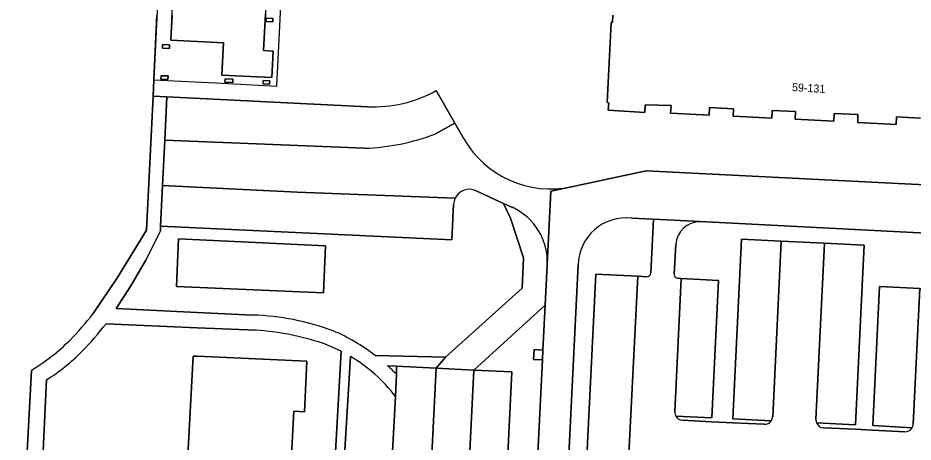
# Model space of a CAD drawing. Extents: x 161758 to 162722, y 384793 to 385405.
# Drawn here: x 161977.6 to 162089.5, y 385196.7 to 385249.7 of the extents above; entities that cross this region are included whole.
import ezdxf

# ---------------------------------------------------------------- set-up
doc = ezdxf.new("R2010")
doc.units = 0
for name, color, linetype in [('IMGEO_Erf', 7, 'Continuous'), ('IMGEO_Grasland_overig', 7, 'Continuous'), ('IMGEO_Groenvoorziening', 7, 'Continuous'), ('IMGEO_Pand', 7, 'Continuous'), ('IMGEO_Pand_nummerreeks', 7, 'Continuous'), ('IMGEO_Pand_overbouw', 7, 'Continuous'), ('IMGEO_Parkeervlak_open', 7, 'Continuous'), ('IMGEO_Rijbaan_lokaal_open', 7, 'Continuous'), ('IMGEO_Voetpad_open', 7, 'Continuous')]:
    doc.layers.add(name, color=color, linetype=linetype)

msp = doc.modelspace()

# ---------------------------------------------------------------- linework, layer by layer
at = {"layer": 'IMGEO_Erf'}
for points in [[(162046.78, 385228.58), (162056.08, 385230.58), (162089.27, 385228.91), (162119.21, 385227.48), (162120.58, 385255.07), (162121.52, 385275.66)], [(161993.66, 385223.17), (161994.48, 385239.89), (161994.58, 385241.94), (161994.97, 385250)], [(161994.97, 385250), (161994.58, 385241.94), (161994.48, 385239.89), (161996.2, 385239.8), (162021.28, 385238.58)], [(162008.52, 385250.18), (162008.29, 385245.58), (162009.5, 385245.52), (162009.33, 385242.21), (162003.07, 385242.52), (162003.27, 385246.56), (162000, 385246.72), (161996.7, 385246.89), (161996.86, 385250)], [(162090.36, 385237.16), (162087.39, 385237.32), (162087.34, 385236.37), (162082.53, 385236.62), (162082.57, 385237.59), (162079.6, 385237.71), (162079.55, 385236.76), (162074.73, 385237), (162074.77, 385237.97), (162071.83, 385238.09), (162071.79, 385237.15), (162066.96, 385237.39), (162067.01, 385238.33), (162064.01, 385238.47), (162063.96, 385237.53), (162059.16, 385237.78), (162059.21, 385238.72), (162055.96, 385238.82), (162055.93, 385237.87), (162051.36, 385238.14), (162051.42, 385239.07), (162051.22, 385239.1), (162051.71, 385249.1), (162051.88, 385249.1), (162051.93, 385250)], [(162029.86, 385240.58), (162032.18, 385236.54), (162033.31, 385234.57)], [(162040.78, 385219.71), (162039.13, 385224.67), (162038.29, 385226.51), (162034.86, 385228.09)], [(162032.03, 385226.37), (162031.81, 385221.96), (161995.42, 385223.67), (161995.39, 385223.09), (161993.57, 385219.42), (161991.69, 385216.2), (161989.87, 385213.4), (162000, 385212.9), (162006.94, 385212.56)], [(161986.98, 385212.75), (161990.02, 385217.24), (161993.66, 385223.17)], [(162022.22, 385207.53), (162031.04, 385207.3), (162040.59, 385215.92), (162040.78, 385219.71)], [(162007.35, 385210.66), (162000, 385210.99), (161988.6, 385211.49)], [(161981.18, 385204.49), (161980, 385179.69), (161982.83, 385179.54), (161985.81, 385179.38), (161985.88, 385180.71), (161988.86, 385180.55), (161988.93, 385181.91), (161991.96, 385181.75), (161992.03, 385183.14), (161995.24, 385182.97), (161995.39, 385185.95), (161998.34, 385185.8), (161999.48, 385207.45)], [(161999.48, 385207.45), (162000, 385207.43), (162013.69, 385206.82), (162013.41, 385200.48), (162012.08, 385200.55), (162011.09, 385181.64), (162016.49, 385181.38), (162017.99, 385208.04)], [(161977.59, 385173.79), (161979.29, 385205.66)]]:
    msp.add_lwpolyline(points, dxfattribs=at)
for points in [[(162009.46, 385249.59), (162009.43, 385249.17), (162008.58, 385249.21), (162008.61, 385249.64)], [(161996.55, 385246.31), (161996.53, 385245.85), (161995.65, 385245.9), (161995.67, 385246.35)], [(161996.36, 385242.41), (161996.34, 385241.96), (161995.46, 385242), (161995.48, 385242.45)], [(162004.45, 385242.03), (162004.43, 385241.6), (162003.45, 385241.65), (162003.47, 385242.07)], [(162009.07, 385241.81), (162009.05, 385241.38), (162008.22, 385241.42), (162008.24, 385241.85)], [(162015.78, 385215.32), (161997.42, 385216.14), (161997.66, 385222.07), (162016.03, 385221.19)]]:
    msp.add_lwpolyline(points, close=True, dxfattribs=at)
for centre, radius, start, end in [((162022.06, 385254.63), 16.07, 267.2007, 299.0331), ((162044.19, 385240.89), 12.58, 210.1487, 281.8576), ((162034.03, 385226.27), 2, 65.3426, 153.9899), ((162034.05, 385226.26), 2.02, 154.131, 177.0709), ((161953, 385239.24), 43.09, 316.225, 322.0594), ((162006.08, 385181.47), 31.1, 69.4775, 88.4165), ((161953.08, 385239.16), 45.03, 316.2341, 322.0816), ((162005.14, 385177.12), 33.62, 71.7297, 86.233), ((162007.09, 385187.73), 24.92, 52.6237, 66.6023), ((161964.64, 385229.39), 27.88, 301.6987, 314.3122), ((162008.93, 385190.22), 19.99, 63.0543, 70.2735), ((161967.52, 385226.13), 25.59, 302.2532, 314.9367)]:
    msp.add_arc(centre, radius, start, end, dxfattribs=at)
at = {"layer": 'IMGEO_Grasland_overig'}
for points in [[(162024.92, 385206.18), (162023.78, 385206.23)], [(162024.89, 385205.17), (162024.92, 385206.18)]]:
    msp.add_lwpolyline(points, dxfattribs=at)
msp.add_arc((162007.3, 385187.96), 24.61, 44.3667, 47.9501, dxfattribs=at)
at = {"layer": 'IMGEO_Groenvoorziening'}
for points in [[(162056.68, 385217.82), (162057.02, 385224.52), (162054.26, 385224.66)], [(162091.9, 385222.76), (162062.84, 385224.23)], [(162071.73, 385199.36), (162066.93, 385199.62), (162068.03, 385222.05), (162072.98, 385221.81), (162078.39, 385221.54), (162083.34, 385221.3), (162083.09, 385216.22), (162082.24, 385198.84), (162077.39, 385199.1)], [(162059.8, 385221.38), (162059.61, 385217.67)], [(162047.62, 385218.82), (162041.98, 385104.58), (162045.02, 385104.42), (162045.2, 385104.41), (162048.36, 385104.25)], [(162048.31, 385105.21), (162045.34, 385105.36), (162045.15, 385105.37), (162044.27, 385105.42), (162049.8, 385217.66), (162055.05, 385217.4)], [(162055.05, 385217.4), (162056.15, 385217.34)], [(162060.09, 385217.15), (162060.49, 385217.13), (162065.15, 385216.9), (162064.31, 385199.75), (162059.81, 385199.94)], [(162089.33, 385198.5), (162084.41, 385198.77), (162085.26, 385216.11), (162090.28, 385215.86), (162091.05, 385215.83)], [(162043.14, 385206.97), (162042.03, 385207.03), (162042.09, 385208.25), (162043.2, 385208.2), (162043.48, 385213.78), (162034.55, 385205.7), (162039.31, 385205.47), (162036.81, 385154.15), (162032.02, 385154.29), (162030.75, 385130.88), (162030.52, 385127.16)], [(162019.15, 385207.4), (162017.59, 385181.32), (162023.62, 385181.03), (162024.79, 385202.4)], [(162039.22, 385129.2), (162039.38, 385132.01), (162043.14, 385206.97)], [(162060.63, 385199.43), (162064.28, 385199.25), (162066.91, 385199.13), (162070.86, 385198.93)], [(162078.26, 385198.49), (162082.22, 385198.3), (162084.38, 385198.19), (162088.41, 385197.99)]]:
    msp.add_lwpolyline(points, dxfattribs=at)
for centre, radius, start, end in [((162053.57, 385218.75), 5.95, 83.3807, 179.2642), ((162062.8, 385221.22), 3, 89.244, 177.0607), ((162056.17, 385217.85), 0.505, 267.7544, 356.5094), ((162060.11, 385217.65), 0.499, 176.9571, 267.3181), ((162008.94, 385190.23), 19.98, 37.5275, 59.2711), ((162060.68, 385200.43), 0.997, 209.3025, 267.2649), ((162070.91, 385199.93), 1, 267.2313, 324.9443), ((162078.31, 385199.49), 1, 202.6886, 267.134), ((162088.45, 385199), 1, 267.3236, 330.4891)]:
    msp.add_arc(centre, radius, start, end, dxfattribs=at)
at = {"layer": 'IMGEO_Pand'}
for points in [[(161996.86, 385250), (161996.7, 385246.89), (162000, 385246.72), (162003.27, 385246.56), (162003.07, 385242.52), (162009.33, 385242.21), (162009.5, 385245.52), (162008.29, 385245.58), (162008.52, 385250.18)], [(162051.93, 385250), (162051.88, 385249.1), (162051.71, 385249.1), (162051.22, 385239.1), (162051.42, 385239.07), (162051.36, 385238.14), (162055.93, 385237.87), (162055.96, 385238.82), (162059.21, 385238.72), (162059.16, 385237.78), (162063.96, 385237.53), (162064.01, 385238.47), (162067.01, 385238.33), (162066.96, 385237.39), (162071.79, 385237.15), (162071.83, 385238.09), (162074.77, 385237.97), (162074.73, 385237), (162079.55, 385236.76), (162079.6, 385237.71), (162082.57, 385237.59), (162082.53, 385236.62), (162087.34, 385236.37), (162087.39, 385237.32), (162090.36, 385237.16)], [(162011.09, 385181.64), (162012.08, 385200.55), (162013.41, 385200.48), (162013.69, 385206.82), (162000, 385207.43), (161999.48, 385207.45), (161998.34, 385185.8)]]:
    msp.add_lwpolyline(points, dxfattribs=at)
for points in [[(162009.46, 385249.59), (162008.61, 385249.64), (162008.58, 385249.21), (162009.43, 385249.17)], [(161996.55, 385246.31), (161995.67, 385246.35), (161995.65, 385245.9), (161996.53, 385245.85)], [(161996.36, 385242.41), (161995.48, 385242.45), (161995.46, 385242), (161996.34, 385241.96)], [(162004.45, 385242.03), (162003.47, 385242.07), (162003.45, 385241.65), (162004.43, 385241.6)], [(162009.07, 385241.81), (162008.24, 385241.85), (162008.22, 385241.42), (162009.05, 385241.38)]]:
    msp.add_lwpolyline(points, close=True, dxfattribs=at)
at = {"layer": 'IMGEO_Pand_overbouw'}
msp.add_lwpolyline([(161996.7, 385246.89), (161999.09, 385295.28), (161997.18, 385295.37), (161994.58, 385241.94), (162003.1, 385241.51), (162009.95, 385241.16), (162010.78, 385257.89), (162008.91, 385257.98), (162008.52, 385250.18), (162008.29, 385245.58), (162009.5, 385245.52), (162009.33, 385242.21), (162003.07, 385242.52), (162003.27, 385246.56)], close=True, dxfattribs=at)
at = {"layer": 'IMGEO_Parkeervlak_open'}
for points in [[(162021.28, 385238.58), (161996.2, 385239.8), (161995.94, 385234.41), (162020.92, 385233.39)], [(162032.18, 385236.54), (162029.86, 385240.58)], [(162029.71, 385235.16), (162032.18, 385236.54)], [(162032.23, 385227.15), (162012.49, 385227.9), (161995.66, 385228.72), (161995.42, 385223.67), (162031.81, 385221.96), (162032.03, 385226.37)], [(162072.98, 385221.81), (162068.03, 385222.05), (162066.93, 385199.62), (162071.73, 385199.36)], [(162071.91, 385199.88), (162072.98, 385221.81)], [(162078.39, 385221.54), (162077.31, 385199.54)], [(162077.39, 385199.1), (162082.24, 385198.84), (162083.09, 385216.22), (162083.34, 385221.3), (162078.39, 385221.54)], [(162055.05, 385217.4), (162049.8, 385217.66), (162044.27, 385105.42), (162045.15, 385105.37), (162045.34, 385105.36), (162048.31, 385105.21)], [(162049.36, 385104.7), (162055.05, 385217.4)], [(162060.49, 385217.13), (162059.68, 385200.48)], [(162059.81, 385199.94), (162064.31, 385199.75), (162065.15, 385216.9), (162060.49, 385217.13)], [(162090.28, 385215.86), (162085.26, 385216.11), (162084.41, 385198.77), (162089.33, 385198.5)], [(162089.46, 385198.94), (162090.28, 385215.86)], [(162029.85, 385205.93), (162024.92, 385206.18), (162024.89, 385205.17), (162024.79, 385202.4), (162023.62, 385181.03), (162026.61, 385180.88)], [(162028.71, 385182.78), (162029.85, 385205.93)]]:
    msp.add_lwpolyline(points, dxfattribs=at)
msp.add_lwpolyline([(162034.55, 385205.7), (162032.02, 385154.29), (162036.81, 385154.15), (162039.31, 385205.47)], close=True, dxfattribs=at)
for centre, radius, start, end in [((162022.06, 385254.63), 16.07, 267.2007, 299.0331), ((162020.03, 385260.55), 27.17, 271.8635, 290.8566), ((162034.05, 385226.26), 2.02, 154.131, 177.0709), ((162060.67, 385200.43), 0.993, 177.0092, 209.46), ((162070.91, 385199.93), 0.998, 324.9271, 357.1565), ((162078.32, 385199.49), 1.01, 177.3282, 202.5371), ((162088.46, 385198.99), 0.997, 330.502, 357.1968)]:
    msp.add_arc(centre, radius, start, end, dxfattribs=at)
at = {"layer": 'IMGEO_Rijbaan_lokaal_open'}
for points in [[(162033.31, 385234.57), (162032.18, 385236.54), (162029.71, 385235.16)], [(162020.92, 385233.39), (161995.94, 385234.41), (161995.66, 385228.72), (162012.49, 385227.9), (162032.23, 385227.15)], [(162043.74, 385218.82), (162044.2, 385228.02), (162046.78, 385228.58)], [(162034.86, 385228.09), (162038.29, 385226.51), (162039.38, 385226.01)], [(162062.84, 385224.23), (162057.02, 385224.52), (162056.68, 385217.82)], [(162077.31, 385199.54), (162078.39, 385221.54), (162072.98, 385221.81), (162071.91, 385199.88)], [(162059.61, 385217.67), (162059.8, 385221.38)], [(162056.15, 385217.34), (162055.05, 385217.4), (162049.36, 385104.7)], [(162059.68, 385200.48), (162060.49, 385217.13), (162060.09, 385217.15)], [(162091.05, 385215.83), (162090.28, 385215.86), (162089.46, 385198.94)], [(162034.55, 385205.7), (162029.85, 385205.93), (162028.71, 385182.78)], [(162030.52, 385127.16), (162030.75, 385130.88), (162032.02, 385154.29), (162034.55, 385205.7)], [(162070.86, 385198.93), (162066.91, 385199.13), (162064.28, 385199.25), (162060.63, 385199.43)], [(162088.41, 385197.99), (162084.38, 385198.19), (162082.22, 385198.3), (162078.26, 385198.49)]]:
    msp.add_lwpolyline(points, dxfattribs=at)
for centre, radius, start, end in [((162020.03, 385260.55), 27.17, 271.8635, 290.8566), ((162044.19, 385240.89), 12.58, 210.1487, 281.8576), ((162034.03, 385226.27), 2, 65.3426, 153.9899), ((162036.2, 385219.17), 7.55, 357.386, 65.0628), ((162062.8, 385221.22), 3, 89.244, 177.0607), ((162056.17, 385217.85), 0.505, 267.7544, 356.5094), ((162060.11, 385217.65), 0.499, 176.9571, 267.3181), ((162060.67, 385200.43), 0.993, 177.0092, 209.46), ((162060.68, 385200.43), 0.997, 209.3025, 267.2649), ((162070.91, 385199.93), 1, 267.2313, 324.9443), ((162070.91, 385199.93), 0.998, 324.9271, 357.1565), ((162078.32, 385199.49), 1.01, 177.3282, 202.5371), ((162078.31, 385199.49), 1, 202.6886, 267.134), ((162088.45, 385199), 1, 267.3236, 330.4891), ((162088.46, 385198.99), 0.997, 330.502, 357.1968)]:
    msp.add_arc(centre, radius, start, end, dxfattribs=at)
at = {"layer": 'IMGEO_Voetpad_open'}
for points in [[(162006.94, 385212.56), (162000, 385212.9), (161989.87, 385213.4), (161991.69, 385216.2), (161993.57, 385219.42), (161995.39, 385223.09), (161995.42, 385223.67), (161995.66, 385228.72), (161995.94, 385234.41), (161996.2, 385239.8), (161994.48, 385239.89), (161993.66, 385223.17), (161990.02, 385217.24), (161986.98, 385212.75)], [(162054.26, 385224.66), (162057.02, 385224.52), (162062.84, 385224.23), (162091.9, 385222.76), (162092.09, 385222.75), (162097.16, 385222.5), (162118.91, 385221.44), (162119.21, 385227.48), (162089.27, 385228.91), (162056.08, 385230.58), (162046.78, 385228.58), (162044.2, 385228.02), (162043.74, 385218.82), (162043.48, 385213.78), (162043.2, 385208.2), (162043.14, 385206.97), (162039.38, 385132.01), (162039.22, 385129.2)], [(162039.38, 385226.01), (162038.29, 385226.51), (162039.13, 385224.67), (162040.78, 385219.71), (162040.59, 385215.92), (162031.04, 385207.3), (162029.85, 385205.93), (162034.55, 385205.7), (162043.48, 385213.78)], [(162040, 385065.39), (162040.05, 385066.31), (162041.62, 385097.36), (162041.67, 385098.19), (162041.79, 385100.78), (162041.8, 385100.87), (162041.98, 385104.58), (162047.62, 385218.82)], [(162043.48, 385213.78), (162043.74, 385218.82)], [(161988.6, 385211.49), (162000, 385210.99), (162007.35, 385210.66)], [(162017.99, 385208.04), (162016.49, 385181.38), (162017.59, 385181.32), (162019.15, 385207.4)], [(162023.78, 385206.23), (162024.92, 385206.18), (162029.85, 385205.93), (162031.04, 385207.3), (162022.22, 385207.53)], [(161979.29, 385205.66), (161977.59, 385173.79)], [(162024.79, 385202.4), (162024.89, 385205.17)], [(161979.69, 385173.74), (161980, 385179.69), (161981.18, 385204.49)]]:
    msp.add_lwpolyline(points, dxfattribs=at)
for points in [[(161997.66, 385222.07), (161997.42, 385216.14), (162015.78, 385215.32), (162016.03, 385221.19)], [(162043.2, 385208.2), (162042.09, 385208.25), (162042.03, 385207.03), (162043.14, 385206.97)]]:
    msp.add_lwpolyline(points, close=True, dxfattribs=at)
for centre, radius, start, end in [((162036.2, 385219.17), 7.55, 357.386, 65.0628), ((162053.57, 385218.75), 5.95, 83.3807, 179.2642), ((161953, 385239.24), 43.09, 316.225, 322.0594), ((162006.08, 385181.47), 31.1, 69.4775, 88.4165), ((161953.08, 385239.16), 45.03, 316.2341, 322.0816), ((162005.14, 385177.12), 33.62, 71.7297, 86.233), ((162007.09, 385187.73), 24.92, 52.6237, 66.6023), ((161964.64, 385229.39), 27.88, 301.6987, 314.3122), ((162008.93, 385190.22), 19.99, 63.0543, 70.2735), ((161967.52, 385226.13), 25.59, 302.2532, 314.9367), ((162008.94, 385190.23), 19.98, 37.5275, 59.2711), ((162007.3, 385187.96), 24.61, 44.3667, 47.9501)]:
    msp.add_arc(centre, radius, start, end, dxfattribs=at)

# ---------------------------------------------------------------- texts
at = {"layer": 'IMGEO_Pand_nummerreeks'}
msp.add_text('59-131', height=1, rotation=356.8899, dxfattribs=at).set_placement((162074.3, 385240.52))

doc.saveas('drawing.dxf')
